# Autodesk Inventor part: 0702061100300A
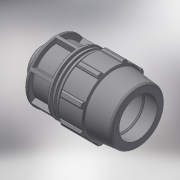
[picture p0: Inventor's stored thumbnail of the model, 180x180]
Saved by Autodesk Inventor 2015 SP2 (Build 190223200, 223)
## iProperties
Created: 2017-02
Part Number: 0702061100300A
Material: Generic
Description: PLASSON MALE ADAPTOR 110-3"
Document SubType Name: Modeling
Designer: KIM
Mass: 964.158 g
Surface Area: 1468.9 cm^2
Volume: 964.158 cm^3
Density: 1 g/cm^3
Appearance: Default
Author: KIM
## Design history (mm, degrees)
derived "87020.ipt"
feature "Solid1::87020.ipt"
tag "TaggingFeature1"
body "Solid1"
other parameters: "d4" = 36.57143, "d5" = 64, "d7" = 181, "d8" = 135.75, "d9" = 36.57143, "d11" = 7.31429, "d12" = 144.8, "d13" = 120 deg, "d14" = 143, "d15" = 6 deg, "d16" = 162.9, "d18" = 5.5, "d19" = 35 deg, "d20" = 17.5 deg, "d21" = 168.33, "d23" = 0, "d25" = 360 deg, "d27" = 3.62, "d34" = 9.05, "d36" = 0, "d42" = 76.8, "d43" = 5.43, "d46" = 3.3, "d49" = 213, "d51" = 256, "d52" = 34, "d53" = 2.2, "d55" = 360 deg, "d57" = 87.884, "d58" = 61.5188, "d59" = 51.2, "d61" = 159.642, "d62" = 3.07429, "d63" = 3.07429, "d66" = 6.14857, "E_" = 181, "H_" = 256, "l_" = 213, "l_2" = 34, "R_" = 87.884, "d60" = 15.37143
